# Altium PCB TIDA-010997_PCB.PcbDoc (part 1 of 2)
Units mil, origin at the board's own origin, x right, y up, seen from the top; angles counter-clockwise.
Board outline 2300 x 1800 mil, 2 copper layers (Top Layer, Bottom Layer), stack 62 mil thick; 121 components, 80 nets, 346 pads, 277 vias.
Unrouted connection lines stored in the file: 141.
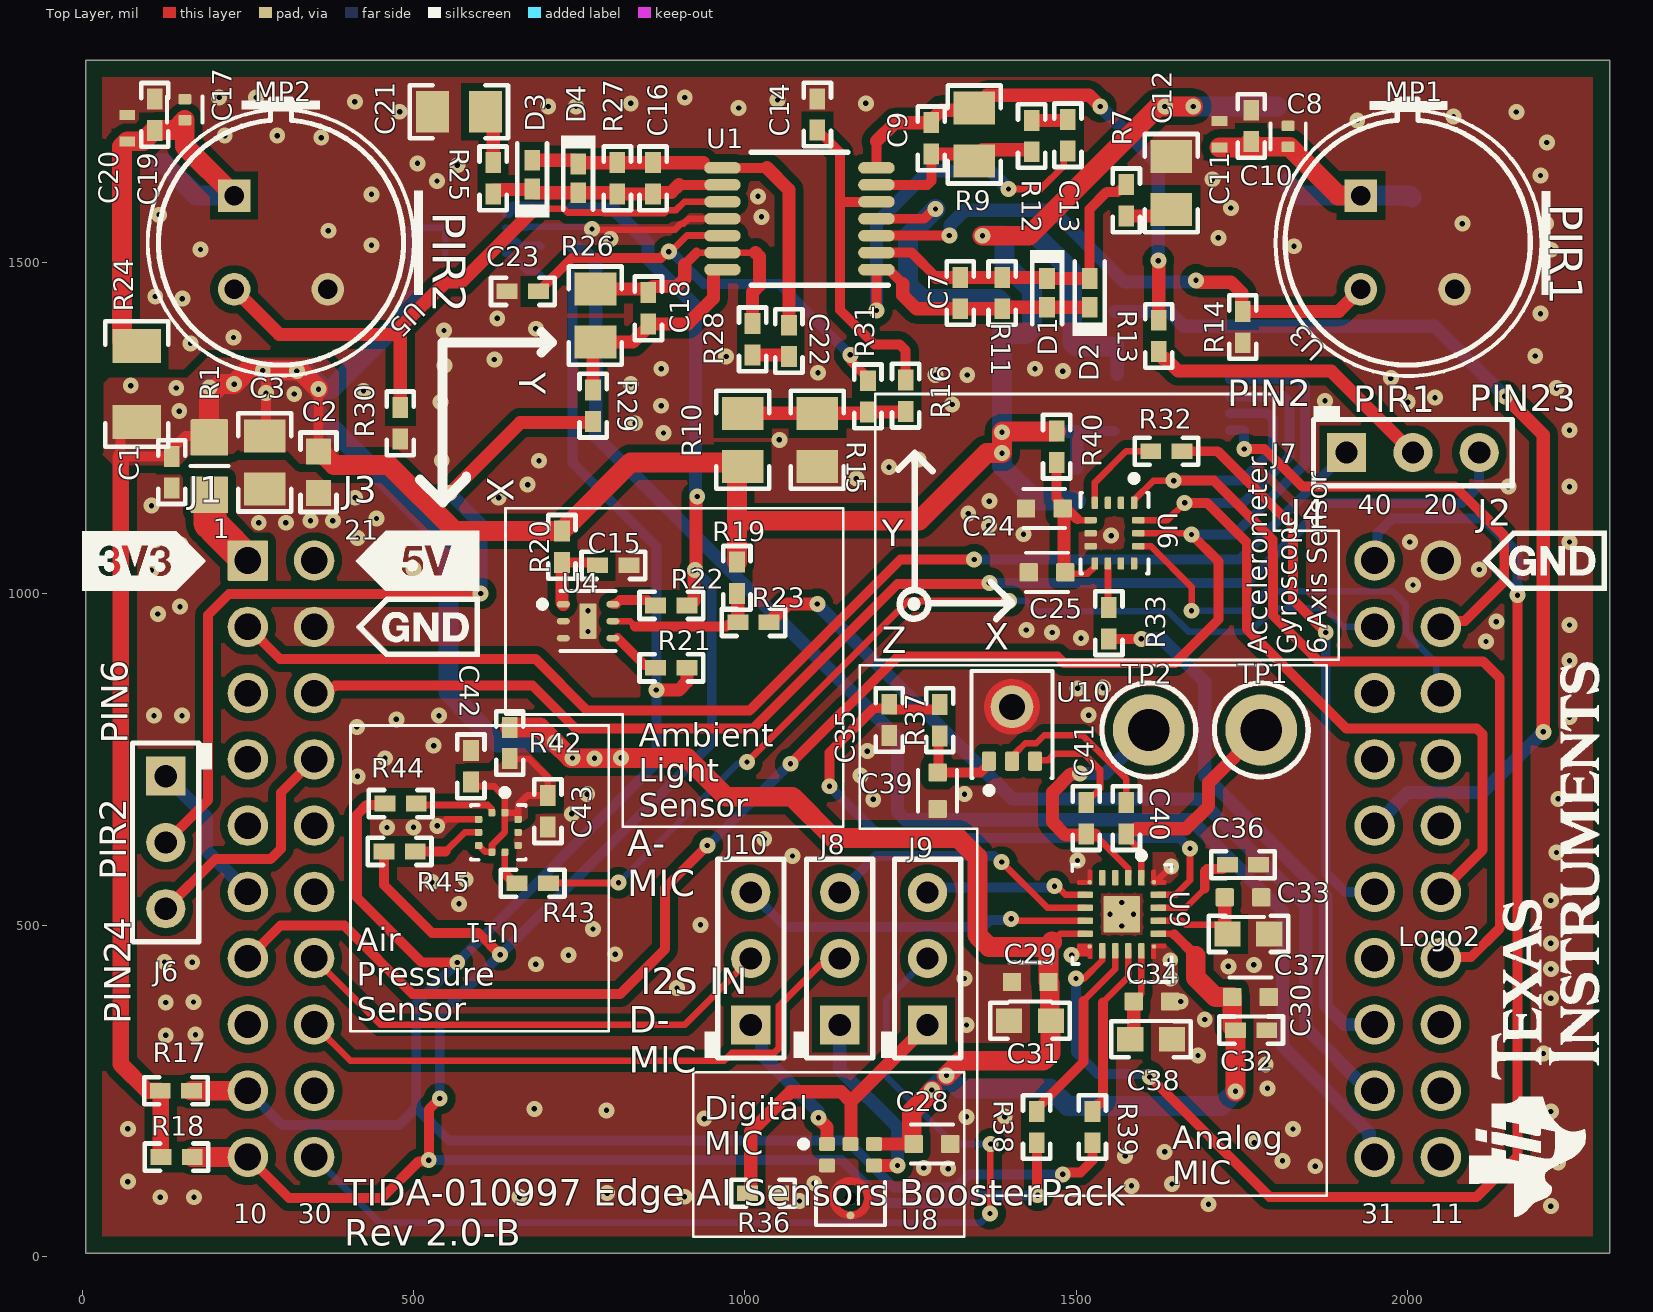
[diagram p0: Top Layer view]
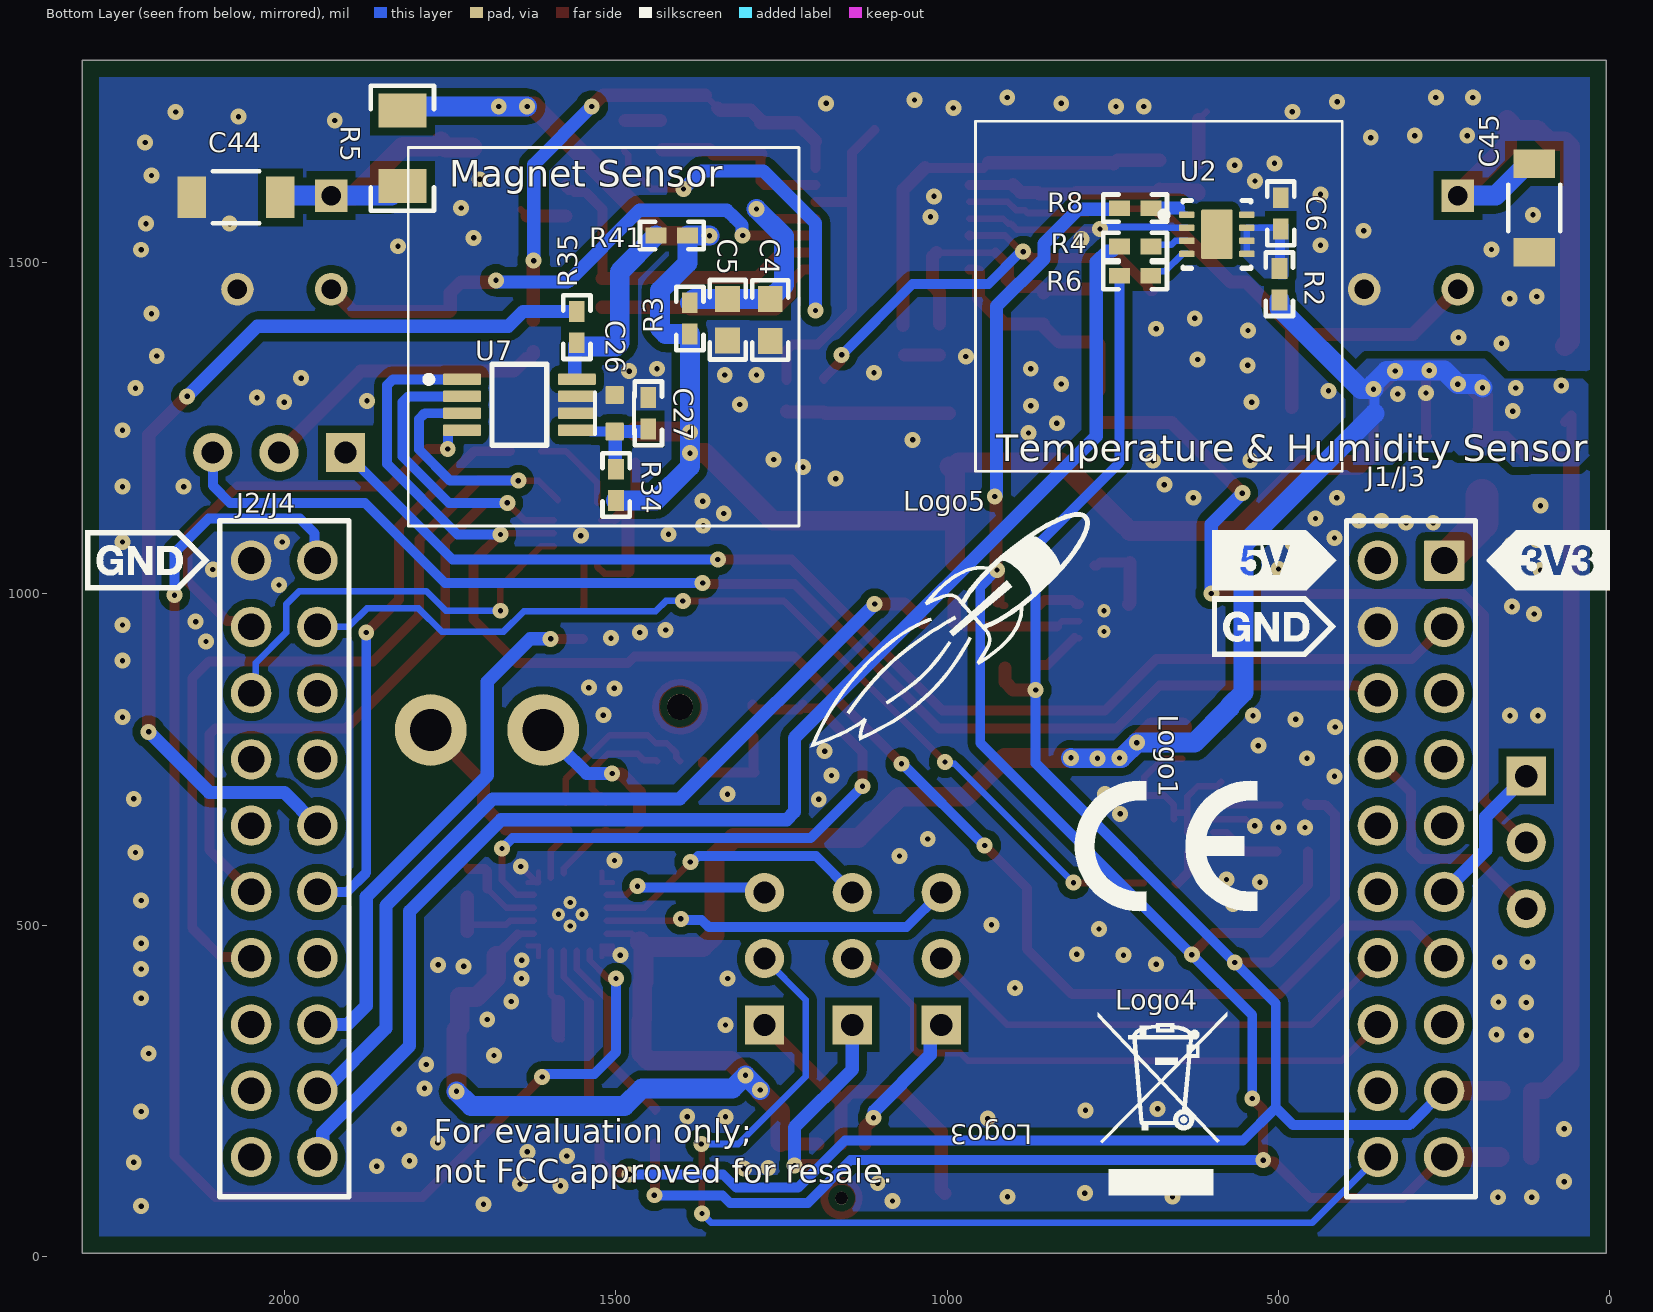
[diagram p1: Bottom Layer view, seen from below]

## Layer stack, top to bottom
Top Solder: solder mask 0.4, Solder Resist, Dk 3.5
Top Layer: signal copper 1.4
Dielectric1: core 59.2, FR-4 High Tg, Dk 4.8
Bottom Layer: signal copper 1.4
Bottom Solder: solder mask 0.4, Solder Resist, Dk 3.5

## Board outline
5,5 2305,5 2305,1805 5,1805

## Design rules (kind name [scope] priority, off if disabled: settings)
AcuteAngle [All] p1: minimum=4.50000000000000E+0001 checktracksonly=FALSE
AssemblyTestPointUsage [All] p1: valid=2
BoardOutlineClearance BoardOutlineClearance_MountingHoles [OnCopper and InComponentClass('Mounting Holes')] p1: gap=39.37 ignorepadtopadclearanceinfootprint=FALSE
BoardOutlineClearance BoardOutlineClearance_Poly [OnCopper and IsPoly] p2: gap=25 ignorepadtopadclearanceinfootprint=FALSE
BoardOutlineClearance [OnCopper and Not InComponentClass('Logo') and not InComponentClass('FiducialMark') and not InRegion(1000,500,4000,800) and not InPoly] p3: gap=40 ignorepadtopadclearanceinfootprint=FALSE
Clearance Clearance_Keepouts [((IsTrack Or IsArc) And Not InPoly) And IsFree and IsKeepOut vs ((IsTrack Or IsArc) And Not InPoly) And IsFree and IsKeepOut] p1: gap=0 ignorepadtopadclearanceinfootprint=FALSE
Clearance Clearance_Poly [InPolygon] p2: gap=12 ignorepadtopadclearanceinfootprint=TRUE
Clearance Clearance_FiducialMark [IsKeepOut and InComponentClass('FiducialMark') vs IsPad and InComponentClass('FiducialMark')] p3: gap=0 ignorepadtopadclearanceinfootprint=FALSE
Clearance [All] p4: gap=7.87 ignorepadtopadclearanceinfootprint=TRUE
ComponentClearance ComponentClearance_MountingHoles_FiducialMarks [InComponentClass('Mounting Holes') vs InComponentClass('FiducialMark')] p1: gap=50 collisioncheckmode=3 verticalgap=10 showdistances=FALSE
ComponentClearance ComponentClearance_Shunt [InComponentClass('Header') vs InComponentClass('Shunt')] p2: gap=0 collisioncheckmode=3 verticalgap=0 showdistances=FALSE
ComponentClearance ComponentClearance_Logo [InComponentClass('Logo')] p3: gap=0 collisioncheckmode=3 verticalgap=10 showdistances=FALSE
ComponentClearance ComponentClearance_ScrewToNut [(HasFootprint('NY PMS 440 0025 PH')) vs (HasFootprint('Keystone_1902C'))] p4: gap=5 collisioncheckmode=3 verticalgap=10 showdistances=FALSE
ComponentClearance ComponentClearance_MountingHoles [InComponentClass('Mounting Holes')] p5: gap=100 collisioncheckmode=3 verticalgap=100000 showdistances=FALSE
ComponentClearance ComponentClearance_SmallPassives [HasFootprint('0201*') or HasFootprint('0402*') or HasFootprint('0508') or HasFootprint('0603*') or HasFootprint('0612') or HasFootprint('0805*') or HasFootprint('0815*') or HasFootprint('0830*') or HasFootprint('1206*') or HasFootprint('1210*') or HasFootprint('1808*') or HasFootprint('1812*') or HasFootprint('1825*') or HasFootprint('2010*') or HasFootprint('2220*') or HasFootprint('2225*') or HasFootprint('2512*') or HasFootprint('2728*') or HasFootprint('3518*') vs HasFootprint('0201*') or HasFootprint('0402*') or HasFootprint('0508') or HasFootprint('0603*') or HasFootprint('0612') or HasFootprint('0805*') or HasFootprint('0815*') or HasFootprint('0830*') or HasFootprint('1206*') or HasFootprint('1210*') or HasFootprint('1808*') or HasFootprint('1812*') or HasFootprint('1825*') or HasFootprint('2010*') or HasFootprint('2220*') or HasFootprint('2225*') or HasFootprint('2512*') or HasFootprint('2728*') or HasFootprint('3518*')] p6: gap=14.96 collisioncheckmode=3 verticalgap=10 showdistances=FALSE
ComponentClearance ComponentClearance_THtoSMT [IsThruComponent vs IsSMTComponent] p7: gap=0 collisioncheckmode=3 verticalgap=0 showdistances=FALSE
ComponentClearance ComponentClearance_THtoTH [IsThruComponent vs IsThruComponent] p8: gap=0 collisioncheckmode=3 verticalgap=30 showdistances=FALSE
ComponentClearance [All] p9: gap=0 collisioncheckmode=3 verticalgap=0 showdistances=FALSE
DiffPairsRouting [All] p1: maxlimit=100 minlimit=10 mostfreqgap=10 toplayer_minwidth=15 toplayer_maxwidth=15 toplayer_prefwidth=15 bottomlayer_minwidth=15 bottomlayer_maxwidth=15 bottomlayer_prefwidth=15 maxuncoupledlength=1000
FabricationTestPointUsage TestPointUsage [All] p1: valid=2 allowmultiple=FALSE
FabricationTestpoint Testpoint [All] p1: side=3 testpointundercomponent=TRUE minsize=40 maxsize=100 preferedsize=60 minholesize=0 maxholesize=40 preferedholesize=32 testpointgrid=1 allowsidetop=TRUE allowsidebottom=TRUE usegrid=TRUE gridtolerance=0.01
FanoutControl Fanout_LCC [IsLCC] p1: bgadir=Out bgaviamode=Centered fanoutstyle=Auto fanoutdirection=Alternating viagrid=1 // Fanout_LCC (Default Rule)
FanoutControl Fanout_BGA [IsBGA] p2: bgadir=Out bgaviamode=Centered fanoutstyle=Auto fanoutdirection=Alternating viagrid=1 // Fanout_BGA (Default Rule)
FanoutControl Fanout_Default [All] p4: bgadir=Out bgaviamode=Centered fanoutstyle=Auto fanoutdirection=Alternating viagrid=1 // Fanout_Default (Default Rule)
FanoutControl Fanout_Small [(CompPinCount < 5)] p5: bgadir=Out bgaviamode=Centered fanoutstyle=Auto fanoutdirection=OutThenIn viagrid=1 // Fanout_Small (Default Rule)
Height [All] p1: minheight=0 maxheight=1000 prefheight=10
HoleSize [All] p1: absolutevalues=TRUE maxlimit=251 minlimit=7.87 maxpercent=80.000 minpercent=20.000
MinimumAnnularRing MinimumAnnularRing_ThermalPadVias [IsVia and InAnyComponent] p1: minimumring=5.91
MinimumAnnularRing [All] p2: minimumring=4
MinimumSolderMaskSliver MinimumSolderMaskSliver_Logo [InComponentClass('Logo') vs InComponentClass('Logo')] p1: minsoldermaskwidth=0.7
MinimumSolderMaskSliver [All] p2: minsoldermaskwidth=3.94
PlaneConnect [All] p1: planeconnectstyle=Direct reliefexpansion=10 reliefentries=4 reliefconductorwidth=10 reliefairgap=10
PolygonConnect [All] p1: connectstyle=Direct reliefconductorwidth=10 reliefentries=4 polygonreliefangle="90 Angle" airgapwidth=10
RoutingVias ThermalPadVias [IsVia and InAnyComponent] p1: holewidth=7.87 width=19.68 viastyle="Through Hole" minholewidth=7.87 minwidth=19.68 maxholewidth=12.99 maxwidth=23.62
RoutingVias [All] p2: holewidth=16 width=34 viastyle="Through Hole" minholewidth=6 minwidth=15 maxholewidth=40 maxwidth=65
SilkToBoardRegionClearance [Not ((IsComment or IsDesignator) And (Hide <> 'False')) and not InRegion(1000,500,4000,800)] p1:
SilkToSilkClearance SilkToSilkClearance_Pb-FreeLogo [(HasFootprint('Pb-Free_Overlay_Medium') OR HasFootprint('Pb-Free_Overlay_Small')) vs (HasFootprint('Pb-Free_Overlay_Medium') OR HasFootprint('Pb-Free_Overlay_Small'))] p1: silktosilkclearance=0
SilkToSilkClearance [All] p2: silktosilkclearance=3.94
SilkToSolderMaskClearance SilkToComponentPadClearance [(IsPad or IsFill or IsRegion) and InAnycomponent] p1: minsilkscreentomaskgap=5 clearancetoexposedcopper=TRUE
SilkToSolderMaskClearance "Silk to Solder Mask Opening" [All] p2: minsilkscreentomaskgap=3.94 clearancetoexposedcopper=FALSE
SolderMaskExpansion [All] p1: expansion=1.97 istentingtop=FALSE
SupplyNets "Schematic Supply Nets_3" [InNet('3V3_EVM')] p1: voltage=0.000
SupplyNets "Schematic Supply Nets_1" [InNet('GND')] p2: voltage=0.000
UnRoutedNet [All] p1: checkbadconnections=TRUE
Width [All] p1: maxlimit=100 minlimit=6 preferedwidth=15 checkconnectedcopper=TRUE
13 further rules are at their usual default settings.

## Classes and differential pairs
net class GND: GND
component class TIDA-010997_Audio_Air_pressure: C28 C29 C30 C31 C32 C33 C34 C35 C36 C37 C38 C39 C40 C41 C42 C43 J8 J9 J10 R36 R37 R38 R39 R42 R43 R44 R45 TP1 TP2 U8 U9 U10 U11
component class Logo: Logo2
component class TIDA-010997_Sensors: C4 C5 C6 C7 C8 C9 C10 C11 C12 C13 C14 C15 C16 C17 C18 C19 C20 C21 C22 C23 C24 C25 C26 C27 C44 C45 D1 D2 D3 D4 Logo1 Logo2 Logo3 Logo4 Logo5 MP1 MP2 R2 R3 R4 R5 R6 R7 R8 R9 R10 R11 R12 R13 R14 R15 R16 R19 R20 R21 R22 R23 R24 R25 R26 R27 R28 R29 R30 R31 R32 R33 R34 R35 R40 R41 U1 U2 U3 U4 U5 U6 U7
component class TIDA-010997_Connector: C1 C2 C3 J1/J3 J2/J4 J6 J7 R1 R17 R18
component class Header: J6 J7 J8 J9 J10

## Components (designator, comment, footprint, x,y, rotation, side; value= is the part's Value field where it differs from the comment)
C1 "GRM155R61A103KA01D" 0402 135.09,1183.24 r270 top value=0.01uF
C2 "06033D104KAT2A" 0603 356.5,1183.16 r270 top value=0.1uF
C3 "C2012X7R1A106K125AC" 0805_HV 275.5,1198 r270 top value=10uF
C4 "C0603C104J3RAC" 0603 1266.73,1412.94 r270 bottom value=0.1uF
C5 "0603ZC103KAT2A" 0603 1331.11,1413.28 r270 bottom value=0.01uF
C6 "CC0402KRX7R8BB104" 0402 496.46,1573.86 r90 bottom value=0.1uF
C7 "GRM155R71H103KA88D" 0402 1325,1453.51 r90 top value=0.01uF
C8 "GRT1555C1H120JA02D" FP-GRT1555C1H120JA02D_0402-MFG 1819.54,1690.03 r270 top value=12pF
C9 "CC0402KRX7R8BB472" 0402 1281.19,1687.12 r270 top value=4700pF
C10 "CC0402KRX7R8BB104" 0402 1763.81,1705.78 r90 top value=0.1uF
C11 "GRM155R61A106ME21D" 0402_070 1715.91,1693.35 r90 top value=10uF
C12 "C2012X5R1A336M125AC" 0805_HV 1643.21,1619.59 r90 top value=33uF
C13 "C1005X5R1A335K050BC" 0402 1487.27,1691.71 r270 top value=3.3uF
C14 "C1005X7R1H104K050BE" 0402 1109.29,1723.05 r90 top value=0.1uF
C15 "CC0402KRX7R8BB104" 0402 801.31,1042.74 r0 top value=0.1uF
C16 "GRM155R71H103KA88D" 0402 861.34,1626.7 r270 top value=0.01uF
C17 "GRT1555C1H120JA02D" FP-GRT1555C1H120JA02D_0402-MFG 154.8,1730.25 r270 top value=12pF
C18 "CC0402KRX7R8BB472" 0402 854.3,1430.63 r90 top value=4700pF
C19 "CC0402KRX7R8BB104" 0402 109.46,1722.59 r90 top value=0.1uF
C20 "GRM155R61A106ME21D" 0402_070 67.95,1702.59 r90 top value=10uF
C21 "C2012X5R1A336M125AC" 0805_HV 568.46,1727.12 r180 top value=33uF
C22 "C1005X5R1A335K050BC" 0402 1066.37,1381.35 r90 top value=3.3uF
C23 "C1005X7R1H104K050BE" 0402 664.84,1456.13 r180 top value=0.1uF
C24 "C1608X8R1E104K080AA" FP-C1608X8R1E104K080AA_0603-MFG 1451.78,1128.35 r0 top value=100nF
C25 "C1608X8R1E104K080AA" FP-C1608X8R1E104K080AA_0603-MFG 1455.85,1032.25 r0 top value=100nF
C26 "C1608X8R1E104K080AA" FP-C1608X8R1E104K080AA_0603-MFG 1501.6,1272.22 r270 bottom value=100nF
C27 "C1005X6S1C105K050BC" 0402 1450.66,1272.22 r90 bottom value=1uF
C28 "C1608X8R1E104K080AA" FP-C1608X8R1E104K080AA_0603-MFG 1282.22,169.61 r180 top value=100nF
C29 "C1608X8R1E104K080AA" FP-C1608X8R1E104K080AA_0603-MFG 1430.49,414.1 r0 top value=100nF
C30 "C1608X8R1E104K080AA" FP-C1608X8R1E104K080AA_0603-MFG 1762.78,391.43 r180 top value=100nF
C31 "GRM188R61C106MAALD" 0603 1430.15,355.73 r180 top value=10uF
C32 "C1005X6S1C105K050BC" 0402 1763.76,341.43 r0 top value=1uF
C33 "C1608X8R1E104K080AA" FP-C1608X8R1E104K080AA_0603-MFG 1751.49,541.77 r0 top value=100nF
C34 "C1608X8R1E104K080AA" FP-C1608X8R1E104K080AA_0603-MFG 1614.12,384.57 r0 top value=100nF
C35 "C1005X6S1C105K050BC" 0402 1217.76,809.55 r270 top value=1uF
C36 "C1005X6S1C105K050BC" 0402 1751.49,590.98 r0 top value=1uF
C37 "GRM188R61C106MAALD" 0603 1759.55,486.65 r180 top value=10uF
C38 "GRM188R61C106MAALD" 0603 1612.91,327.78 r180 top value=10uF
C39 "C1608X8R1E104K080AA" FP-C1608X8R1E104K080AA_0603-MFG 1290.74,702.67 r90 top value=100nF
C40 "C1005X6S1C105K050BC" 0402 1575.53,661.17 r270 top value=1uF
C41 "C1005X6S1C105K050BC" 0402 1514.85,661.24 r270 top value=1uF
C42 "CC0402KRX7R8BB104" 0402 586.54,739.57 r90 top value=0.1uF
C43 "CC0402KRX7R8BB104" 0402 702.68,671.86 r270 top value=0.1uF
C44 "C3216X5R0J107M160AB" 1206_190 2072.83,1598.03 r0 bottom value=100uF
C45 "C3216X5R0J107M160AB" 1206_190 114.09,1581.99 r270 bottom value=100uF
D1 "1N4148X-TP" SOD-523 1455.85,1453.87 r270 top value=75V
D2 "1N4148X-TP" SOD-523 1520.16,1453.87 r90 top value=75V
D3 "1N4148X-TP" SOD-523 678.92,1632.34 r90 top value=75V
D4 "1N4148X-TP" SOD-523 748.33,1626.7 r270 top value=75V
J1/J3 "SSQ-110-03-T-D" BoosterPack_40pin_J1J3 299.96,600 r180 bottom locked
J2/J4 "SSQ-110-03-T-D" BoosterPack_40pin_J2J4 2000,600 r180 bottom locked
J6 "800-10-003-10-001000" Mill-Max_800-10-003-10-001000 126.04,624.66 r270 top
J7 "800-10-003-10-001000" Mill-Max_800-10-003-10-001000 2007.87,1212.96 r0 top
J8 "800-10-003-10-001000" Mill-Max_800-10-003-10-001000 1142.99,449.33 r90 top
J9 "800-10-003-10-001000" Mill-Max_800-10-003-10-001000 1275.52,449.33 r90 top
J10 "800-10-003-10-001000" Mill-Max_800-10-003-10-001000 1008.84,449.33 r90 top
Logo1 "CE Mark" CE_Mark_5mm 669.62,619.19 r180 bottom
Logo2 "Texas Instruments" TI_Stacked_Overlay_Small 2191.21,478.18 r90 top
Logo3 "FCC disclaimer" FCC_disclaimer 956.51,1084.52 r270 bottom
Logo4 "WEEE logo" WEEE_Minimum 676.97,264.5 r180 bottom
Logo5 "LaunchPad Rocket" LaunchPadRocket_Small 966.44,969.5 r180 bottom
MP1 "IML-0685" FP-IML-0685_LENS_IRA-S-MFG 2001.21,1529.13 r0 top
MP2 "IML-0685" FP-IML-0685_LENS_IRA-S-MFG 299.7,1529.61 r0 top
R1 "HCJ0805ZT0R00" FP-HCJ0805ZT0R00_0805-MFG 192,1192.37 r270 top value=0
R2 "CRCW04020000Z0ED" 0402 498.46,1466.89 r270 bottom value=0
R3 "CRCW04020000Z0ED" 0402 1387.99,1415.3 r90 bottom value=0
R4 "CRCW04020000Z0ED" 0402 716.16,1523.85 r0 bottom value=0
R5 "CRCW1206619KFKEA" 1206 1821.68,1672.02 r90 bottom value=619k
R6 "CRCW04020000Z0ED" 0402 716.21,1479.94 r180 bottom value=0
R7 "RC0402FR-076K81L" 0402 1575.53,1593.53 r90 top value=6.81k
R8 "CRCW04020000Z0ED" 0402 716.16,1581.82 r180 bottom value=0
R9 "ERJ-6ENF1804V" 0805_HV 1345.87,1692.85 r90 top value=1.80Meg
R10 "RMCF0805JT15M0" 0805_HV 996.64,1232.08 r270 top value=15Meg
R11 "RC0402FR-071M5L" 0402 1387.99,1453.59 r270 top value=1.50Meg
R12 "CRCW040268K1FKED" 0402 1432.53,1690.46 r270 top value=68.1k
R13 "CRCW04020000Z0ED" 0402 1624.34,1388.87 r270 top value=0
R14 "CRCW04021M30FKED" 0402 1751.27,1402.33 r90 top value=1.30Meg
R15 "RMCF0805JT15M0" 0805_HV 1109.29,1232.08 r270 top value=15Meg
R16 "CRCW04020000Z0ED" 0402 1242.38,1298.71 r270 top value=0
R17 "AC0402FR-0710KL" 0402 141.46,250 r180 top value=10.0k
R18 "AC0402FR-0710KL" 0402 142.46,150 r180 top value=10.0k
R19 "AC0402FR-0710KL" 0402 987.9,1024 r90 top value=10.0k
R20 "CRCW04020000Z0ED" 0402 723.87,1070.74 r90 top value=0
R21 "CRCW04020000Z0ED" 0402 888.87,887.99 r0 top value=0
R22 "CRCW04020000Z0ED" 0402 888.87,982.24 r0 top value=0
R23 "CRCW04020000Z0ED" 0402 1012.9,956.75 r0 top value=0
R24 "CRCW1206619KFKEA" 1206 82.29,1316.42 r270 top value=619k
R25 "RC0402FR-076K81L" 0402 620.08,1626.7 r270 top value=6.81k
R26 "ERJ-6ENF1804V" 0805_HV 774.33,1419.63 r270 top value=1.80Meg
R27 "RC0402FR-071M5L" 0402 807.58,1626.7 r90 top value=1.50Meg
R28 "CRCW040268K1FKED" 0402 1011.48,1383.85 r90 top value=68.1k
R29 "CRCW04020000Z0ED" 0402 770.83,1283.68 r270 top value=0
R30 "CRCW04021M30FKED" 0402 479.96,1257.13 r90 top value=1.30Meg
R31 "CRCW04020000Z0ED" 0402 1185.62,1297.71 r270 top value=0
R32 "CRCW04020000Z0ED" 0402 1635.95,1214.91 r180 top value=0
R33 "CRCW04020000Z0ED" 0402 1549.14,955.51 r90 top value=0
R34 "CRCW04020000Z0ED" 0402 1499.43,1164.08 r270 bottom value=0
R35 "CRCW04020000Z0ED" 0402 1558.57,1402.2 r270 bottom value=0
R36 "RC1005F104CS" 0402 1027.23,95.41 r180 top value=100k
R37 "CRCW04020000Z0ED" 0402 1293.89,809.16 r90 top value=0
R38 "CRCW04020000Z0ED" 0402 1440.09,195.13 r270 top value=0
R39 "CRCW04020000Z0ED" 0402 1524.32,195.13 r270 top value=0
R40 "CRCW04020000Z0ED" 0402 1470.29,1221.75 r90 top value=0
R41 "RC0402FR-074K7L" 0402 1415.35,1540.45 r180 bottom value=4.70k
R42 "CRCW04020000Z0ED" 0402 645.05,774.65 r90 top value=0
R43 "CRCW04020000Z0ED" 0402 679.69,562.94 r0 top value=0
R44 "CRCW04020000Z0ED" 0402 480.46,683.31 r0 top value=0
R45 "CRCW04020000Z0ED" 0402 478.96,611.07 r0 top value=0
TP1 "5123" Keystone_5123 1779.04,794.38 r0 top
TP2 "5123" Keystone_5123 1609.38,794.38 r0 top
U1 "TLV8544PWR" PW0014A_N 1082.24,1565.73 r180 top
U2 "HDC3020DEF" DEF0008A-MFG 592.96,1542.17 r180 bottom
U3 "IRA-S210ST01" Murata_IRA-E700ST0 2000,1530 r270 top
U4 "OPT4001DNPRQ1" DNP0006A-MFG 763.25,958.49 r0 top
U5 "IRA-S210ST01" Murata_IRA-E700ST0 300,1530 r270 top
U6 "BMI270" FP-BMI270_LGA14-MFG 1557.53,1091.26 r270 top
U7 "TMAG5170A1QDGKR" DGK0008A-MFG 1645.19,1285.02 r180 bottom
U8 "ICS-43434" FP-ICS-43434_LGA_CAV6-MFG 1159.26,115.91 r270 top
U9 "TAA3020IRTER" RTE0020A-MFG 1568.62,516.18 r270 top
U10 "ICS-40740" FP-ICS-40740_LGA4-MFG 1402.93,802.5 r0 top
U11 "BMP384" FP-BMP384_LGA10-MFG 627.88,639.84 r270 top

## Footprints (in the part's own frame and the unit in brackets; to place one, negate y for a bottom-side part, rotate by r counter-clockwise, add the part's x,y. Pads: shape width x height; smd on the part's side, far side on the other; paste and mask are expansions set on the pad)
0402 [mm] "0402 from SM-752 data"
  rect 0.8x0.6 smd: 1(-0.6,0) 2(0.6,0)
  silkscreen extent -1.22,-0.52 1.22,0.52, body extent -0.55,-0.3 0.55,0.3, height 0.6
0402_070 [mil] "SMD, 2-Leads, Body 1.2x0.7mm, Height 0.7mm"
  rect 15x24 smd: 1(-20,0) 2(20,0)
  body extent -24,-14 24,14, height 28
0603 [mm] "0603 from SM-752 data"
  rect 1x0.95 smd: 1(-0.8,0) 2(0.8,0)
  silkscreen extent -1.52,-0.69 1.52,0.69, body extent -0.87,-0.47 0.87,0.47, height 1
0805_HV [mil] "0805 with 30mil clearance between pads"
  rect 50x63 smd: 1(-40,0) 2(40,0)
  silkscreen extent -74,-40 74,40, body extent -43,-29 43,29, height 57
1206 [mm] "1206 from SM-752 data"
  rect 1.3x1.85 smd: 1(-1.45,0) 2(1.45,0)
  silkscreen extent -2.4,-1.21 2.4,1.21, body extent -1.7,-0.9 1.7,0.9, height 1.35
1206_190 [mm] "1206_190"
  rect 1.1x1.6 smd: 1(-1.7,0) 2(1.7,0)
  silkscreen extent -0.9,-1 0.9,1, body extent -1.75,-0.95 1.75,0.95, height 1.9
BoosterPack_40pin_J1J3 [mm] "Receptacle, 2.54mm, 10x2, TH"
  rrect6% 1.55x1.55 hole 1.02: 1(1.27,11.43)
  round 1.55 hole 1.02: 2(1.27,8.89) 3(1.27,6.35) 4(1.27,3.81) 5(1.27,1.27) 6(1.27,-1.27) 7(1.27,-3.81) 8(1.27,-6.35) 9(1.27,-8.89) 10(1.27,-11.43) 21(-1.27,11.43) 22(-1.27,8.89) 23(-1.27,6.35) 24(-1.27,3.81) 25(-1.27,1.27) 26(-1.27,-1.27) 27(-1.27,-3.81) 28(-1.27,-6.35) 29(-1.27,-8.89) 30(-1.27,-11.43)
  silkscreen extent -7.62,-12.95 7.62,12.95, body extent -2.48,-12.95 2.48,12.95, height 8.51
BoosterPack_40pin_J2J4 [mm] "Receptacle, 2.54mm, 10x2, TH"
  round 1.55 hole 1.02: 11(-1.27,-11.43) 12(-1.27,-8.89) 13(-1.27,-6.35) 14(-1.27,-3.81) 15(-1.27,-1.27) 16(-1.27,1.27) 17(-1.27,3.81) 18(-1.27,6.35) 19(-1.27,8.89) 20(-1.27,11.43) 31(1.27,-11.43) 32(1.27,-8.89) 33(1.27,-6.35) 34(1.27,-3.81) 35(1.27,-1.27) 36(1.27,1.27) 37(1.27,3.81) 38(1.27,6.35) 39(1.27,8.89) 40(1.27,11.43)
  silkscreen extent -7.62,-12.95 2.48,12.95, body extent -2.48,-12.95 2.48,12.95, height 8.51
CE_Mark_5mm [mil] "Minimum text height for CE Mark"
  silkscreen extent -138,-98 138,98
DEF0008A-MFG [mm]
  rrect40% 0.6x0.25 smd paste+0 mask+0: 1(-1.15,0.75) 2(-1.15,0.25) 3(-1.15,-0.25) 4(-1.15,-0.75) 5(1.15,-0.75) 6(1.15,-0.25) 7(1.15,0.25) 8(1.15,0.75)
  rrect8% 1.2x1.9 smd paste-1000 mask+0: 9(0,0)
  silkscreen extent -2.15,-1.3 1.3,1.3, body extent -1.25,-1.25 1.25,1.25, height 0.8
DGK0008A-MFG [mm]
  rrect22% 1.45x0.45 smd paste+0 mask+0: 1(-2.2,0.975) 2(-2.2,0.325) 3(-2.2,-0.325) 4(-2.2,-0.975) 5(2.2,-0.975) 6(2.2,-0.325) 7(2.2,0.325) 8(2.2,0.975)
  silkscreen extent -3.6,-1.55 1.05,1.55, body extent -2.45,-1.5 2.45,1.5, height 1.1
DNP0006A-MFG [mm]
  rrect100% 0.5x0.25 smd paste+0 mask+0: 1(-0.95,0.65) 2(-0.95,0) 3(-0.95,-0.65) 4(0.95,-0.65) 5(0.95,0) 6(0.95,0.65)
  rrect15% 0.65x1.35 smd paste-1000 mask+0: 7(0,0)
  silkscreen extent -1.87,-1.15 1.05,1.15, body extent -1.3,-1.15 1.3,1.15, height 0.25
FCC_disclaimer [mil]
FP-BMI270_LGA14-MFG [mm] "Recommended Land Pattern"
  rrect40% 0.475x0.25 smd paste+0 mask+0: 1(-1.162,0.75) 2(-1.162,0.25) 3(-1.162,-0.25) 4(-1.162,-0.75) 8(1.162,-0.75) 9(1.162,-0.25) 10(1.162,0.25) 11(1.162,0.75)
  rrect40% 0.25x0.475 smd paste+0 mask+0: 5(-0.5,-0.913) 6(0,-0.913) 7(0.5,-0.913) 12(0.5,0.913) 13(0,0.913) 14(-0.5,0.913)
  silkscreen extent -2.22,-1.3 1.55,1.3, body extent -1.5,-1.25 1.5,1.25, height 0.87
FP-BMP384_LGA10-MFG [mm] "Recommended Land Pattern"
  rrect37% 0.285x0.27 smd paste+0 mask+0: 1(-0.757,0.25) 2(-0.757,-0.25) 6(0.757,-0.25) 7(0.757,0.25)
  rrect37% 0.27x0.285 smd paste+0 mask+0: 3(-0.5,-0.757) 4(0,-0.757) 5(0.5,-0.757) 8(0.5,0.757) 9(0,0.757) 10(-0.5,0.757)
  silkscreen extent -1.65,-1.05 1.05,1.05, body extent -1,-1 1,1, height 1
FP-C1608X8R1E104K080AA_0603-MFG [mm]
  rrect14% 0.7x0.7 smd paste+0 mask+0: 1(-0.7,0) 2(0.7,0)
  silkscreen extent -0.8,-0.75 0.8,0.75, body extent -1.15,-0.55 1.15,0.55, height 0.25
FP-GRT1555C1H120JA02D_0402-MFG [mm]
  rrect25% 0.4x0.5 smd paste+0 mask+0: 1(-0.4,0) 2(0.4,0)
  silkscreen extent -0.5,-0.67 0.5,0.67, body extent -0.7,-0.38 0.7,0.38, height 0.25
FP-HCJ0805ZT0R00_0805-MFG [mm]
  rrect7% 1.4x1.44 smd paste+0 mask+0: 1(-1.1,0) 2(1.1,0)
  silkscreen extent 0,-0.72 0,0.72, body extent -1.9,-0.82 1.9,0.82, height 0.25
FP-ICS-40740_LGA4-MFG [mm]
  rrect19% 0.53x0.73 smd paste-1000 mask+0: 1(-0.88,-1.405) 2(0,-1.405) 3(0.88,-1.405)
  round 1.636 smd paste-1000 mask-1000: 4(0,0.68)
  round 1 hole 1 unplated paste-2539.97 mask+0: ""(0,0.68)
  Top Layer circle w0.3: c0,0.68 r0.92
  silkscreen extent -1.55,-2.64 1.55,2.05, body extent -1.5,-2 1.5,2, height 1.22
FP-ICS-43434_LGA_CAV6-MFG [mm]
  rrect19% 0.522x0.6 smd paste-1000 mask+0: 1(-1.364,-0.9) 2(-0.542,-0.9) 4(-0.542,0.9) 5(-1.364,0.9) 6(-1.364,0)
  round 0.3 smd paste-1000 mask-1000: 3(1.372,0)
  round 0.5 hole 0.5 unplated paste-2539.97 mask+0: ""(0.71,0)
  Top Layer circle w0.3: c0.71,0 r0.663
  silkscreen extent -1.49,-1.92 1.75,1.33, body extent -2.25,-1.83 2.25,1.83, height 0.25
FP-IML-0685_LENS_IRA-S-MFG [mil]
  silkscreen extent -201,-201 215,215, body extent -219,-219 219,219, height 10
Keystone_5123 [mm] "Keystone"
  round 2.75 hole 1.6: 1(0,0)
  silkscreen extent -1.8,-1.8 1.8,1.8, body extent -1.59,-1.5 1.59,1.68, height 5.47
LaunchPadRocket_Small [mil]
  silkscreen extent -241,-202 182,153
Mill-Max_800-10-003-10-001000 [mm] "Mill-Max"
  rect 1.5x1.5 hole 0.85: 1(-2.54,0)
  round 1.5 hole 0.85: 2(0,0) 3(2.54,0)
  silkscreen extent -3.81,-1.27 3.81,1.78, body extent -3.81,-1.27 3.81,1.27, height 8.13
Murata_IRA-E700ST0 [mm] "TH, 3-Leads, Dia 9.2mm"
  rect 1.25x1.25 hole 0.75: 1(-1.796,-1.796)
  round 1.25 hole 0.75: 2(1.796,-1.796) 3(1.796,1.796)
  silkscreen extent -5.5,-4.7 4.7,4.7, body extent -5.5,-4.7 4.7,4.7, height 4.9
PW0014A_N [mm] "TSOP, 14-Leads, Body 5x4.4mm, Pitch 0.65mm, IPC Medium Density"
  oval 1.4x0.45 smd: 1(-2.95,1.95) 2(-2.95,1.3) 3(-2.95,0.65) 4(-2.95,0) 5(-2.95,-0.65) 6(-2.95,-1.3) 7(-2.95,-1.95) 8(2.95,-1.95) 9(2.95,-1.3) 10(2.95,-0.65) 11(2.95,0) 12(2.95,0.65) 13(2.95,1.3) 14(2.95,1.95)
  silkscreen extent -3.4,-2.55 1.85,2.55, body extent -3.21,-2.5 3.21,2.5, height 1
RTE0020A-MFG [mm]
  rrect40% 0.6x0.25 smd paste+0 mask+0: 1(-1.4,0.75) 2(-1.4,0.25) 3(-1.4,-0.25) 4(-1.4,-0.75) 11(1.4,-0.75) 12(1.4,-0.25) 13(1.4,0.25) 14(1.4,0.75)
  round 0.171 smd paste+0 mask+0: 5(-1.233,-1.233) 10(1.233,-1.233) 15(1.233,1.233) 20(-1.233,1.233)
  rrect40% 0.25x0.6 smd paste+0 mask+0: 6(-0.75,-1.4) 7(-0.25,-1.4) 8(0.25,-1.4) 9(0.75,-1.4) 16(0.75,1.4) 17(0.25,1.4) 18(-0.25,1.4) 19(-0.75,1.4)
  rrect7% 1.4x1.4 smd paste-1000 mask+0: 21(0,0)
  Top Layer region: -1.65,1.125 -1.669,1.129 -1.685,1.14 -1.696,1.156 -1.7,1.175 -1.7,1.175 -1.7,1.25 -1.693,1.275 -1.675,1.293 -1.65,1.3 -1.65,1.3 -1.3,1.3 -1.3,1.65 -1.293,1.675 -1.275,1.693 -1.25,1.7 -1.25,1.7 -1.175,1.7 -1.15,1.693 -1.132,1.675 -1.125,1.65 -1.125,1.65 -1.125,1.175 -1.129,1.156 -1.14,1.14 -1.156,1.129 -1.175,1.125 -1.175,1.125
  Top Layer region: -1.65,-1.125 -1.669,-1.129 -1.685,-1.14 -1.696,-1.156 -1.7,-1.175 -1.7,-1.175 -1.7,-1.25 -1.693,-1.275 -1.675,-1.293 -1.65,-1.3 -1.65,-1.3 -1.3,-1.3 -1.3,-1.65 -1.293,-1.675 -1.275,-1.693 -1.25,-1.7 -1.25,-1.7 -1.175,-1.7 -1.15,-1.693 -1.132,-1.675 -1.125,-1.65 -1.125,-1.65 -1.125,-1.175 -1.129,-1.156 -1.14,-1.14 -1.156,-1.129 -1.175,-1.125 -1.175,-1.125
  Top Layer region: 1.65,-1.125 1.669,-1.129 1.685,-1.14 1.696,-1.156 1.7,-1.175 1.7,-1.175 1.7,-1.25 1.693,-1.275 1.675,-1.293 1.65,-1.3 1.65,-1.3 1.3,-1.3 1.3,-1.65 1.293,-1.675 1.275,-1.693 1.25,-1.7 1.25,-1.7 1.175,-1.7 1.15,-1.693 1.132,-1.675 1.125,-1.65 1.125,-1.65 1.125,-1.175 1.129,-1.156 1.14,-1.14 1.156,-1.129 1.175,-1.125 1.175,-1.125
  Top Layer region: 1.65,1.125 1.669,1.129 1.685,1.14 1.696,1.156 1.7,1.175 1.7,1.175 1.7,1.25 1.693,1.275 1.675,1.293 1.65,1.3 1.65,1.3 1.3,1.3 1.3,1.65 1.293,1.675 1.275,1.693 1.25,1.7 1.25,1.7 1.175,1.7 1.15,1.693 1.132,1.675 1.125,1.65 1.125,1.65 1.125,1.175 1.129,1.156 1.14,1.14 1.156,1.129 1.175,1.125 1.175,1.125
  silkscreen extent -2.37,-1.9 1.9,1.9, body extent -1.8,-1.8 1.8,1.8, height 0.25
SOD-523 [mm] "NXP Semiconductor recommended land pattern, nominal STEP model"
  rect 0.8x0.6 smd paste-0.05: 1(-0.55,0) 2(0.55,0)
  silkscreen extent -1.65,-0.66 1.2,0.66, body extent -0.8,-0.4 0.8,0.4, height 0.72
TI_Stacked_Overlay_Small [mil]
  silkscreen extent -418,-98 418,98
WEEE_Minimum [mil] "WEEElie bin"
  silkscreen extent -95,-172 99,104

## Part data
C1: library part CMP-0006561-2, "CAP, CERM, 0.01 uF, 10 V, +/- 10%, X5R, 0402", Cap_Case=0402, Manufacturer=MuRata, Supplier Part Number 1=GRM155R61A103KA01D-ND, TempCo=X5R, Tolerance_%=10%, Value1=Unknown, Value2=10V, ValueDisplayed=0.01uF
C2: library part CMP-0006758-5, "CAP, CERM, 0.1 uF, 25 V, +/- 10%, X5R, 0603", Cap_Case=0603, Manufacturer=AVX, Supplier Part Number 1=478-1244-1-ND, TempCo=X5R, Tolerance_%=10%, Value1="0.048 ohm", Value2=25V, ValueDisplayed=0.1uF
C3: library part CMP-0007863-2, "CAP, CERM, 10 uF, 10 V, +/- 10%, X7R, 0805", Cap_Case=0805, Manufacturer=TDK, Supplier Part Number 1=445-6857-1-ND, TempCo=X7R, Tolerance_%=10%, Value1="0.001063 ohm", Value2=10V, ValueDisplayed=10uF
C4: library part CMP-0006855-4, "CAP, CERM, 0.1 uF, 25 V, +/- 5%, X7R, 0603", Cap_Case=0603, Manufacturer=Kemet, Supplier Part Number 1=1650833, TempCo=X7R, Tolerance_%=5%, Value1=Unknown, Value2=25V, ValueDisplayed=0.1uF
C5: library part CMP-0006814-5, "CAP, CERM, 0.01 uF, 10 V, +/- 10%, X7R, 0603", Cap_Case=0603, Manufacturer=AVX, Supplier Part Number 1=478-7938-2-ND, TempCo=X7R, Tolerance_%=10%, Value1=Unknown, Value2=10V, ValueDisplayed=0.01uF
C6 C10 C15 C19 C42 C43: library part CMP-0860555-1, "CAP, CERM, 0.1 µF, 25 V,+/- 10%, X7R, 0402", Cap_Case=0402, Manufacturer=Yageo, TempCo=X7R, Tolerance_%=10%, Value2=25V, ValueDisplayed=0.1µF
C7 C16: library part CMP-0006674-2, "CAP, CERM, 0.01 uF, 50 V, +/- 10%, X7R, 0402", Cap_Case=0402, Manufacturer=MuRata, Supplier Part Number 1=490-4516-1-ND, TempCo=X7R, Tolerance_%=10%, Value1=Unknown, Value2=50V, ValueDisplayed=0.01uF
C8 C17: library part CMP-0120209-1, "Multi-Layer Ceramic Capacitor 12pF 50V C0G ±5% 0402 Paper T/R", Manufacturer=Murata, Operating Temperature Range="-55°C to +125°C", TempCo=30ppm/°C, Temperature Characteristic=C0G, Tolerance_%=5%, ValueDisplayed=12pF
C9 C18: library part CMP-0860557-1, "CAP, CERM, 4700 pF, 25 V,+/- 10%, X7R, 0402", Cap_Case=0402, Manufacturer=Yageo, TempCo=X7R, Tolerance_%=10%, Value2=25V, ValueDisplayed=4700pF
C11 C20: library part CMP-0006565-2, "CAP, CERM, 10 uF, 10 V, +/- 20%, X5R, 0402", Cap_Case=0402, Manufacturer=MuRata, TempCo=X5R, Tolerance_%=20%, Value1=Unknown, Value2=10V, ValueDisplayed=10uF
C12 C21: library part CMP-0007824-2, "CAP, CERM, 33 uF, 10 V, +/- 20%, X5R, 0805", Cap_Case=0805, Manufacturer=TDK, Supplier Part Number 1=445-8238-1-ND, TempCo=X5R, Tolerance_%=20%, Value1="0.001694 ohm", Value2=10V, ValueDisplayed=33uF
C13 C22: library part CMP-0006265-2, "CAP, CERM, 3.3 uF, 10 V, +/- 10%, X5R, 0402", Cap_Case=0402, Manufacturer=TDK, Supplier Part Number 1=445-13819-1-ND, TempCo=X5R, Tolerance_%=10%, Value1="0.004157 ohm", Value2=10V, ValueDisplayed=3.3uF
C14 C23: library part CMP-0064946-2, "CAP, CERM, 0.1 uF, 50 V,+/- 10%, X7R, 0402", Cap_Case=0402, Manufacturer=TDK, Supplier Part Number 1=445-173610-1-ND, TempCo=X7R, Tolerance_%=10%, Value1=Unknown, Value2=50V, ValueDisplayed=0.1uF
C24 C25 C26 C28 C29 C30 C33 C34 C39: library part CMP-0089959-1, "0.1µF ±10% 25V Ceramic Capacitor X8R 0603 (1608 Metric)", Digikey Part Number=445-2500-1-ND, Manufacturer="TDK Corporation", Mouser Part Number=810-C1608X8R1E104K, Operating Temperature Range="-55°C to +150°C", TempCo=15%, Temperature Characteristic=X8R, Tolerance_%=10%, ValueDisplayed=100nF
C27 C32 C35 C36 C40 C41: library part CMP-0006286-2, "CAP, CERM, 1 uF, 16 V, +/- 10%, X6S, 0402", Cap_Case=0402, Manufacturer=TDK, Supplier Part Number 1=445-9086-1-ND, TempCo=X6S, Tolerance_%=10%, Value1="0.011416 ohm", Value2=16V, ValueDisplayed=1uF
C31 C37 C38: library part CMP-0007336-5, "CAP, CERM, 10 uF, 16 V, +/- 20%, X5R, 0603", Cap_Case=0603, Manufacturer=MuRata, Supplier Part Number 1=GRM188R61C106MAALD-ND, TempCo=X5R, Tolerance_%=20%, Value1=Unknown, Value2=16V, ValueDisplayed=10uF
C44 C45: library part CMP-0064957-2, "CAP, CERM, 100 uF, 6.3 V,+/- 20%, X5R, 1206", Cap_Case=1206, Manufacturer=TDK, Supplier Part Number 1=445-6008-1-ND, TempCo=X5R, Tolerance_%=20%, Value1=Unknown, Value2=6.3V, ValueDisplayed=100uF
D1 D2 D3 D4: library part CMP-0076957-3, "Diode, Switching, 75 V, 0.3 A, SOD-523", Manufacturer="Micro Commercial Components", Value1=0.3A, Value2=1.25V
J1/J3: library part CMP-0003837-4, "Receptacle, 2.54mm, 10x2, Tin, TH", Alternate Manufacturer="Major League Electronics", Alternate PartNumber=CRD-081413-A-G, Manufacturer=Samtec, Supplier Part Number 1=SAM1204-10-ND
J2/J4: library part CMP-0078266-4, "Receptacle, 2.54mm, 10x2, Tin, TH", Alternate Manufacturer="Major League Electronics", Alternate PartNumber=CRD-081413-A-G, Manufacturer=Samtec, Supplier Part Number 1=SAM1204-10-ND
J6 J7 J8 J9 J10: library part CMP-0055086-1, "Header, 100mil, 3x1, TH", Manufacturer=Mill-Max, Supplier Part Number 1=ED7203-ND
Logo1: library part CMP-0074844-2, Manufacturer="Texas Instruments"
Logo2: library part CMP-0074838-1, "Texas Instrument Corporate Signature"
Logo3: library part CMP-0074847-1, "FCC_disclaimer"
Logo4: library part CMP-0074769-4, Manufacturer="Texas Instruments"
Logo5: library part CMP-0074846-1, "LaunchPad Rocket logo"
MP1 MP2: library part CMP-0091003-1, "Fresnel Lens, IML Series, Pyroelectric Infrared Sensors, Inline Type", Digikey Part Number=490-12568-ND, Manufacturer=Murata, Mouser Part Number=81-IML-0685, Operating Temperature Range="-25°C to +60°C"
R1: library part CMP-0091603-1, "0 Ohms Jumper 0.5W, 1/2W Chip Resistor 0805 (2012 Metric) Automotive AEC-Q200 Metal Foil", Digikey Part Number=HCJ0805ZT0R00CT-ND, Manufacturer=Stackpole, Operating Temperature Range="-55°C to +155°C", Power=500mW
R2 R3 R4 R6 R8 R13 R16 R20 R21 R22 R23 R29 R31 R32 R33 R34 R35 R37 R38 R39 R40 R42 R43 R44 R45: library part CMP-0026822-3, "RES, 0, 5%, 0.063 W, AEC-Q200 Grade 0, 0402", Manufacturer=Vishay-Dale, Power_W=63mW, Supplier Part Number 1=541-0.0JCT-ND, TempCo="200 ppm/C", Tolerance_%=5%, Value2=0.063W, Value_Code=0000, ValueDisplayed=0
R5 R24: library part CMP-0017103-3, "RES, 619 k, 1%, 0.25 W, AEC-Q200 Grade 0, 1206", Manufacturer=Vishay-Dale, Power_W=250mW, Supplier Part Number 1=541-619KFCT-ND, TempCo="100 ppm/C", Tolerance_%=1%, Value2=0.25W, Value_Code=619k
R7 R25: library part CMP-0078787-1, "RES, 6.81 k, 1%, 0.063 W, 0402", Manufacturer="Yageo America", Power_W=63mW, Supplier Part Number 1=311-6.81KLRCT-ND, TempCo="100 ppm/C", Tolerance_%=1%, Value2=0.063W, Value_Code=6k81, ValueDisplayed=6.81k
R9 R26: library part CMP-0021600-3, "RES, 1.80 M, 1%, 0.125 W, AEC-Q200 Grade 0, 0805", Manufacturer=Panasonic, Power_W=125mW, Supplier Part Number 1=P1.80MCCT-ND, TempCo="100 ppm/C", Tolerance_%=1%, Value2=0.125W, Value_Code=1M80, ValueDisplayed=1.80M
R10 R15: library part CMP-0020831-2, "RES, 15 M, 5%, 0.125 W, AEC-Q200 Grade 0, 0805", Manufacturer="Stackpole Electronics Inc", Power_W=125mW, Supplier Part Number 1=RMCF0805JT15M0CT-ND, TempCo="200 ppm/C", Tolerance_%=5%, Value2=0.125W, Value_Code=15M0, ValueDisplayed=15M
R11 R27: library part CMP-0026726-1, "RES, 1.50 M, 1%, 0.063 W, 0402", Manufacturer="Yageo America", Power_W=63mW, Supplier Part Number 1=RC0402FR-071M5L-ND, TempCo="100 ppm/C", Tolerance_%=1%, Value2=0.063W, Value_Code=1M50, ValueDisplayed=1.50M
R12 R28: library part CMP-0026506-2, "RES, 68.1 k, 1%, 0.063 W, AEC-Q200 Grade 0, 0402", Manufacturer=Vishay-Dale, Power_W=63mW, Supplier Part Number 1=541-68.1KLCT-ND, TempCo="100 ppm/C", Tolerance_%=1%, Value2=0.063W, Value_Code=68k1, ValueDisplayed=68.1k
R14 R30: library part CMP-0026111-2, "RES, 1.30 M, 1%, 0.063 W, AEC-Q200 Grade 0, 0402", Manufacturer=Vishay-Dale, Power_W=63mW, Supplier Part Number 1=541-1.30MLCT-ND, TempCo="100 ppm/C", Tolerance_%=1%, Value2=0.063W, Value_Code=1M30, ValueDisplayed=1.30M
R17 R18 R19: library part CMP-0077731-1, "RES, 10.0 k, 1%, 0.063 W, AEC-Q200 Grade 0, 0402", Manufacturer="Yageo America", Power_W=63mW, Supplier Part Number 1=YAG3436CT-ND, TempCo="100 ppm/C", Tolerance_%=1%, Value2=0.063W, Value_Code=10k0, ValueDisplayed=10.0k
R36: library part CMP-0026745-1, "RES, 100 k, 1%, 0.063 W, 0402", Manufacturer="Samsung Electro-Mechanics", Power_W=63mW, Supplier Part Number 1=1276-3432-1-ND, TempCo="100 ppm/C", Tolerance_%=1%, Value2=0.063W, Value_Code=100k
R41: library part CMP-0026739-1, "RES, 4.70 k, 1%, 0.0625 W, 0402", Manufacturer="Yageo America", Power_W=62.5mW, Supplier Part Number 1=311-4.7KLRCT-ND, TempCo="100 ppm/C", Tolerance_%=1%, Value2=0.0625W, Value_Code=4k70, ValueDisplayed=4.70k
TP1 TP2: library part CMP-0055163-2, "Test Point, Compact, Grey, TH", Color=Grey, Manufacturer="Keystone Electronics", Supplier Part Number 1=36-5123-ND
U1: library part CMP-0013616-3, "500 nA RRIO Nanopower Operational Amplifier, PW0014A (TSSOP-14)", Alternate Manufacturer="Texas Instruments", Alternate PartNumber=TLV8544PWT
U2: library part CMP-0087942-2, "Integrated Humidity and Temperature Digital Sensor", Manufacturer="Texas Instruments", Operating Temperature Range="-45°C to +150°C"
U3 U5: library part CMP-0080109-2, "Pyro Electric Infrared Sensor Fresnel Lens, TH", Manufacturer=MuRata
U4: library part CMP-0096079-1, "High Speed, High Precision, Digital Ambient Light Sensor", Manufacturer="Texas Instruments", Max Supply Voltage=3.6V, Min Supply Voltage=1.6V, Operating Supply Current=1.6-30uA, Operating Temperature Range="-40°C to +85°C"
U6: library part CMP-0126507-1, "Accelerometer, Gyroscope, 6 Axis Sensor I2C, SPI Output", Digikey Part Number=828-1091-1-ND, Manufacturer="Bosch Sensortec", Max Supply Voltage=3.6V, Min Supply Voltage=1.2V, Mouser Part Number=262-BMI270, Operating Supply Current=3-970uA, Operating Temperature Range="-40°C to +85°C"
U7: library part CMP-0088287-1, "3-Axis Linear Hall Effect Sensor With SPI Interface", Manufacturer="Texas Instruments", Max Supply Voltage=5.5V, Min Supply Voltage=1.65V, Operating Supply Current=0.000005-4mA, Operating Temperature Range="-40°C to +150°C"
U8: library part CMP-0120060-1, "60 Hz ~ 20 kHz Digital, I²S Microphone MEMS (Silicon) 1.65 V ~ 3.63 V Omnidirectional (-26 ±1dB @ 94dB SPL) Solder Pads", Current=230-490uA, Digikey Part Number=1428-1066-1-ND, Frequency_Fixed=60-20000Hz, Manufacturer="TDK InvenSense", Max Supply Voltage=3.63V, Min Supply Voltage=1.65V, Mouser Part Number=410-ICS-43434, Operating Temperature Range="-40°C to +85°C"
U9: library part CMP-0123801-1, "2-Channel, 768-kHz, Burr-BrownTM Audio ADC", Manufacturer="Texas Instruments", Max Supply Voltage=3.6V, Min Supply Voltage=1.65V, Operating Temperature Range="-40°C to +125°C"
U10: library part CMP-0089487-2, "77Hz ~ 20kHz Analog Microphone MEMS (Silicon) 1.5V ~ 3.63V Omnidirectional (-37.5dB ±1dB @ 94dB SPL) Solder Pads", Current=155µA, Digikey Part Number=1428-1157-1-ND, Frequency_Fixed=77-20000Hz, Manufacturer=TDK, Max Supply Voltage=3.63V, Min Supply Voltage=1.5V, Mouser Part Number=410-ICS-40740, Operating Supply Voltage=1.5-3.63V, Operating Temperature Range="-40°C to +85°C"
U11: library part CMP-0126884-1, "BMP384 Series 1.8 V 300 to 1250 hPa ±0.5 hPa Barometric Pressure Sensor - LGA-10", Digikey Part Number=828-BMP384CT-ND, Manufacturer="Bosch Sensortec", Max Supply Voltage=3.6V, Min Supply Voltage=1.2V, Mouser Part Number=262-BMP384, Operating Supply Current=700uA, Operating Temperature Range="-40°C to +85°C"

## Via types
v1: diameter 24, hole 8, Top Layer to Bottom Layer, tented both sides, 271 vias
v2: diameter 19.68, hole 7.87, Top Layer to Bottom Layer, tented both sides, 6 vias

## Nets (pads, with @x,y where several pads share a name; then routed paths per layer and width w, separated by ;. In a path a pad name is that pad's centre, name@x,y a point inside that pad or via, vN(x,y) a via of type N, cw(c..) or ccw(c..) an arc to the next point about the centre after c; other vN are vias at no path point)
3V3_EVM: C1.1 C2.1 C3.1 C28.2 C29.2 C30.2 C31.1 C32.1 R1.1 R2.2 R3.1 R5.2 R10.2 R17.2 R18.2 R19.2 R20.2 R24.2 R34.2 R40.2 R41.2 R42.2 U8.5 U9.9 U9.16 | length 8072
  Top Layer w10: 1463.05,474.1 1475.6,486.65 U9.9@1513.5,486.65 ; U9.16@1623.73,486.65 1646.62,486.65 1647.31,485.96
  Top Layer w15: R24.2@67.95,1259.12 57.96,1269.11 57.96,1206.78 C1.1@128.46,1206.78 ; R18.2@118.34,150.5 R18.2@118.84,150 ; C1.1@128.46,1210.72 155.74,1238 189.68,1238 R1.1@192,1235.68 ; v1@273.24,1335.89 273.24,1333.45 277.36,1329.33 v1(277.36,1302.88) 277.36,1239.86 C3.1@275.5,1238 ; C2.1@356.5,1213.67 v1(356.5,1308.68) ; R20.2@723.87,1094.36 723.87,1098.3 728.18,1102.61 R20.2@732.12,1102.61 ; C28.2@1251.71,172.56 C28.2@1254.66,169.61 ; v1(1387.99,1243.58) v1@1388.88,1244.48 ; C29.2@1458.05,414.1 C29.2@1459.84,412.3 ; C31.1@1459.84,357.53 C31.1@1461.64,355.73 ; R40.2@1469.39,1244.48 R40.2@1470.29,1245.37 ; 1647.31,485.96 1648,485.96 1680.24,453.72
  Top Layer w20: U8.5@1194.69,169.61 C28.2@1254.66,169.61
  Top Layer w25: 57.96,1206.78 57.96,290.19 98.15,250 R17.2@117.84,250 ; R18.2@118.34,150.5 R17.2@118.34,249.5
  Top Layer w30: R1.1@192,1235.68 192,1247.71 191.47,1248.24 191.47,1298.63 209.04,1316.21 v1(229.29,1316.21) 249.77,1336.69 v1(272.44,1336.69) 323.06,1336.69 v1(323.86,1335.89) 329.3,1335.89 v1(356.5,1308.68) ; C2.1@356.5,1214.66 356.5,1213.67 360.2,1209.97 364.19,1209.97 379.94,1194.22 462.48,1194.22 562.34,1094.36 R20.2@723.87,1094.36 ; R42.2@645.05,798.27 690.54,798.27 v1(713.62,775.2) 736.69,752.12 v1(739.78,752.12) 740.29,751.61 812.51,751.61 v1(813.12,752.22) 912.93,752.22 971.64,693.51 1071.45,693.51 1133.59,631.37 1321.82,631.37 1350.65,602.54 1350.65,484.73 1368.22,467.16 1458.05,467.16 ; R20.2@732.12,1102.61 827.66,1198.16 R10.2@982.45,1198.16 ; R19.2@987.9,1047.62 987.9,1110 ; R10.2@996.64,1192.08 992.58,1188.03 987.9,1183.34 987.9,1110 ; C28.2@1251.71,172.56 1251.71,218.75 v1@1283.06,250.09 ; v1(1304.11,273.2) 1326.19,295.28 1450,295.28 1460.92,306.19 C31.1@1460.92,355.73 ; v1(1358.41,1540.14) 1428.53,1540.14 1623.52,1735.12 v1(1633.53,1735.12) v1(1676.47,1735.12) ; v1(1387.99,1243.58) v1(1387.99,1212.08) 1364.78,1212.08 1262.7,1110 987.9,1110 ; v1@1388.88,1244.48 R40.2@1469.39,1244.48 ; C29.2@1458.05,414.1 1458.05,421.04 1458.05,467.16 ; C31.1@1459.84,357.53 C29.2@1459.84,412.3 ; 1463.05,475.63 1463.05,474.1 1458.05,469.1 1458.05,467.16 ; 1680.24,453.72 1680.24,420.96 1709.77,391.43 C30.2@1735.22,391.43 1735.22,345.75 1739.54,341.43 C32.1@1740.14,341.43 v1(1740.14,249.06)
  Bottom Layer w15: 355.23,1272.09 355.23,1307.41 v1(356.5,1308.68)
  Bottom Layer w30: v1(191.99,1310.84) 197.36,1316.21 v1(229.29,1316.21) 249.77,1336.69 v1(272.44,1336.69) 323.06,1336.69 v1(323.86,1335.89) 336.82,1335.89 v1@356.5,1316.21 ; 355.23,1272.09 552.89,1074.43 552.89,850.86 573.32,830.43 573.32,828.53 626.65,775.2 v1(713.62,775.2) 736.69,752.12 v1(739.78,752.12) 740.29,751.61 812.51,751.61 v1(813.12,752.22) ; v1(356.5,1308.68) 375.87,1308.68 498.46,1431.28 R2.2@498.46,1443.26 ; v1(1282.03,251.12) v1(1304.11,273.2) 1323.76,253.55 1460.18,253.55 1486.49,227.25 1718.32,227.25 ; v1(1358.41,1540.14) 1358.57,1540.29 1391.58,1540.29 R41.2@1391.73,1540.45 1391.73,1498.99 1433.35,1457.37 1433.35,1400.46 1424.56,1391.67 R3.1@1387.99,1391.67 v1(1387.99,1243.58) v1(1387.99,1212.08) 1387.99,1191.93 1439.46,1140.46 R34.2@1499.43,1140.46 ; v1(1633.53,1735.12) 1803.24,1735.12 v1(1676.47,1735.12) ; 1720.88,229.81 v1(1740.14,249.06)
  other v1: 773.13,751.61 146.46,1275.39 319.96,1301.27 141.96,1310.4 73.29,1313.96
ADC_IN_2: J1/J3.2 J7.1 | length 1871.2
  Top Layer w15: J1/J3.2@249.96,950 298.61,901.35 684.34,901.35 761.73,823.97 1007.18,823.97 1234.75,1051.53 v1(1345.87,1051.53)
  Bottom Layer w15: v1(1345.87,1051.53) 1746.45,1051.53 J7.1@1907.87,1212.96
ADC_IN_6: J1/J3.6 J6.1 | length 226
  Bottom Layer w20: J6.1@126.04,724.66 187.13,663.57 187.13,612.83 J1/J3.6@249.96,550
ADC_IN_23: J1/J3.23 J7.3 | length 1990.5
  Top Layer w15: J1/J3.23@349.96,850 358.77,858.81 379.12,858.81 381.76,861.45 679.6,861.45 744.27,796.77 1012.33,796.77 1230.02,1014.46 1367.02,1014.46 v1(1368.7,1016.14)
  Bottom Layer w15: v1@1369.47,1016.14 1369.7,1016.37 1387.26,1016.37 1387.31,1016.43 1409.99,1016.43 1410.28,1016.14 1757.37,1016.14 1878.26,1137.03 2081.84,1137.03 2107.87,1163.06 J7.3@2107.87,1212.96
ADC_IN_24: J1/J3.24 J6.3 | length 366.9
  Top Layer w15: J6.3@126.04,524.66 201.19,599.81 284.47,599.81 299.73,615.07 299.73,699.77 J1/J3.24@349.96,750
Air_INTR: J2/J4.39 R43.2 | length 1468.5
  Top Layer w10: R43.2@703.31,562.94 703.8,563.43 808.67,563.43 v1(809.15,563.91) ; v1(1003.14,746.06) 1246.13,989.05 v1(1398.65,989.05)
  Bottom Layer w10: v1(809.15,563.91) 988.62,743.38 1000.46,743.38 v1(1003.14,746.06) ; v1(1398.65,989.05) 1398.77,989.18 1424.15,989.18 1439.77,973.56 1638.42,973.56 1669.24,942.74 1762.32,942.74 1797.32,977.75 1875.18,977.75 1902.93,950 J2/J4.39@1950,950
Audio_GPIO: J2/J4.40 U9.11 | length 2149.5
  Top Layer w10: v1(1499.43,419.21) 1511.34,419.21 1539.01,446.88 1539.01,460.98 U9.11@1539.09,461.06
  Top Layer w15: v1(1610.98,270.67) 1791.65,90 2104.14,90 2165.55,151.41 v1(2165.55,997.78)
  Bottom Layer w15: v1(1499.43,419.21) 1499.43,308.11 1531.95,275.59 v1@1609.38,275.59 ; J2/J4.40@1950,1050 1954.16,1054.16 1954.16,1090.81 1976.58,1113.23 2114.06,1113.23 2165.55,1061.73 v1(2165.55,997.78)
GND: C1.2 C2.2 C3.2 C4.2 C5.2 C6.2 C8.1 C10.2 C11.2 C12.2 C14.2 C15.2 C17.1 C19.2 C20.2 C21.2 C23.2 C24.1 C25.1 C26.1 C27.2 C28.1 C29.1 C30.1 C31.2 C32.2 C33.2 C34.2 C35.2 C36.2 C37.1 C38.1 C39.1 C42.2 C43.2 C44.2 C45.2 J1/J3.22 J2/J4.20 R14.1 R15.2 R30.1 R36.1 U1.11 U2.2 U2.8 U3.3 U4.2 U4.3 U4.7 U5.3 U6.6 U6.7 U7.6 U7.7 U8.2 U8.3 U9.5 U9.10 U9.15 U9.20 U9.21 U10.4 U11.3 U11.8 U11.9 | length 494.4
  Top Layer w10: v1(535.73,649.74) 539.52,649.74 549.31,659.52 U11.3@598.06,659.52 ; v1(769.37,1550.24) 770.37,1549.24 894.68,1549.24 903.76,1558.32 907.72,1558.32 915.13,1565.73 U1.11@966.1,1565.73 ; 1517.44,458.11 1516.66,457.33 1495.6,457.33 v1(1492.92,454.65) 1496.71,454.65 1507.05,465 1517.44,465 ; U9.20@1617.15,564.71 1619.62,564.71 v1(1643.21,588.31)
  Bottom Layer w10: U2.2@638.24,1552.01 669.62,1552.01 671.51,1553.9 765.71,1553.9 v1(769.37,1550.24)
  other v1: 2216,75.94 1699.57,78.74 1082.44,83.61 117.84,89.28 168.59,89.28 659.74,90 908.84,90 792.06,95.41 1583.15,106.48 1644.4,109.15 1104.51,110.39 68.9,112.84 1306.64,132.48 1269.75,133.59 1860.52,136.06 2227.16,142.02 1811.02,144.15 1573.64,151.43 1633.3,157.76 1768.55,171.5 1827.04,192.21 68.9,192.51 938.53,207.87 1334.42,210.55 1392.03,210.9 2216,218.68 791.11,220.35 682.31,222.68 1788.59,253.55 1785.88,289.61 1683.56,303.16 2204.72,306.19 126.04,333.59 170.96,334.62 1334.42,349.26 1693.81,357.53 126.04,383.05 167.88,384.02 1657.57,384.57 2216,389.52 897.58,405.15 1331.11,419.21 1642,419.21 2216,433.78 1729.45,437.75 1767.89,439.93 684.56,440.85 124.15,444.4 166.08,443.86 1641.68,446.88 733.91,454.65 804.38,455.95 2216,472.44 770.83,494.08 932.79,500.35 568.65,532.04 2216,537.07 527.9,564.71 578.42,568.83 1501.84,597.5 1071.81,604.13 2224.41,609.48 1029.07,629.76 459.98,647.09 499.89,647.43 738.85,667.75 1193.6,689.61 2227.16,690.35 761.73,697.55 1331.39,697.55 415.29,724.37 1174.38,725.53 456.84,751.68 1184.63,762.38 530.33,770.64 414.46,798.78 474.04,810.39 2244.09,813.67 108.26,815.98 150.46,815.98 538.45,815.98 1518.65,816.72 1501.99,857.09 1540.53,858.2 2244.09,898.88 2118.2,927.83 1507.05,932.9 1463.48,941.43 1424.56,945.25 2244.09,952.74 2133.79,957.85 114.09,969.29 147.46,980.49 2007.87,1013.05 150.46,1033.59 104.65,1035.52 2107.87,1036.49 499.86,1037.11 434.34,1046.76 148.13,1074.48 479.01,1076.1 2003.22,1078.11 2244.09,1078.11 110.01,1080.58 415.29,1084.08 1552.58,1087.5 1420.2,1089.61 1368.07,1102.54 266.37,1106.97 307.36,1106.97 344.36,1110 378.14,1110 444,1113.46 1336.93,1121.07 104.65,1132.77 1368.7,1139.65 411.86,1144.8 628.32,1144.8 2151.96,1161.53 2244.09,1161.53 672.21,1164.57 1168.03,1173.58 1217.43,1190.85 542.46,1201 689.29,1200.59 1261.69,1202.61 1051.84,1232.1 877.06,1242.51 2244.09,1246.63 834.31,1257.2 873.52,1283.61 1312.63,1285.46 540.46,1288.97 2000.04,1289.03 1875.18,1290.91 2041.1,1295.85 424.46,1306.08 2224.41,1310.17 827.66,1316.5 1974.64,1325.27 1287.51,1329.98 1335.44,1329.98 1110.34,1333.4 1479.66,1335.76 873.7,1339.42 1437.57,1339.42 546.46,1344.54 621.89,1353.46 971.64,1357.73 2192.53,1358.71 163.44,1377.67 228.22,1386.56 545.96,1396.96 684.56,1399.8 626.25,1415.52 2200.5,1422.56 151.05,1445.16 110.21,1448.27 178.38,1519.23 2216,1518.89 1828.56,1524.3 436.59,1525.8 797.38,1535.27 1714.35,1536.98 371.37,1547.66 2082.46,1558.35 2208.66,1558.35 1024.87,1568.53 115.94,1571.67 1733.11,1581.82 1019.69,1599.46 436.59,1602.54 535.46,1622.58 1705.21,1625.27 2200.5,1631.04 566.07,1646.52 505.96,1649.31 2210,1680.78 360.68,1688.06 215.16,1691.09 294.24,1691.09 1923.9,1714.08 2069.18,1719.8 479.01,1727.18 2164,1726.76 990.56,1732.69 703.14,1735.12 745.17,1735.12 827.72,1739.87 1182.37,1739.9 411.34,1742.25 1049.14,1745.02 206.7,1748.64 262.5,1748.64 909.2,1748.64
  other v2: 1568.62,498.46 1550.9,516.18 1586.33,516.18 1568.62,533.9 763.25,942.74 763.25,974.24
HDC_INTR: J2/J4.31 R4.2 | length 2134.6
  Bottom Layer w20: R4.2@739.78,1523.85 743.72,1523.85 750.53,1517.03 758.58,1517.03 774.86,1500.76 774.86,1237.71 1230.32,782.25 1230.32,670.76 1242.03,659.05 1672.93,659.05 1811.02,520.96 1811.02,317.71 1942.15,186.58 1942.15,157.85 J2/J4.31@1950,150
